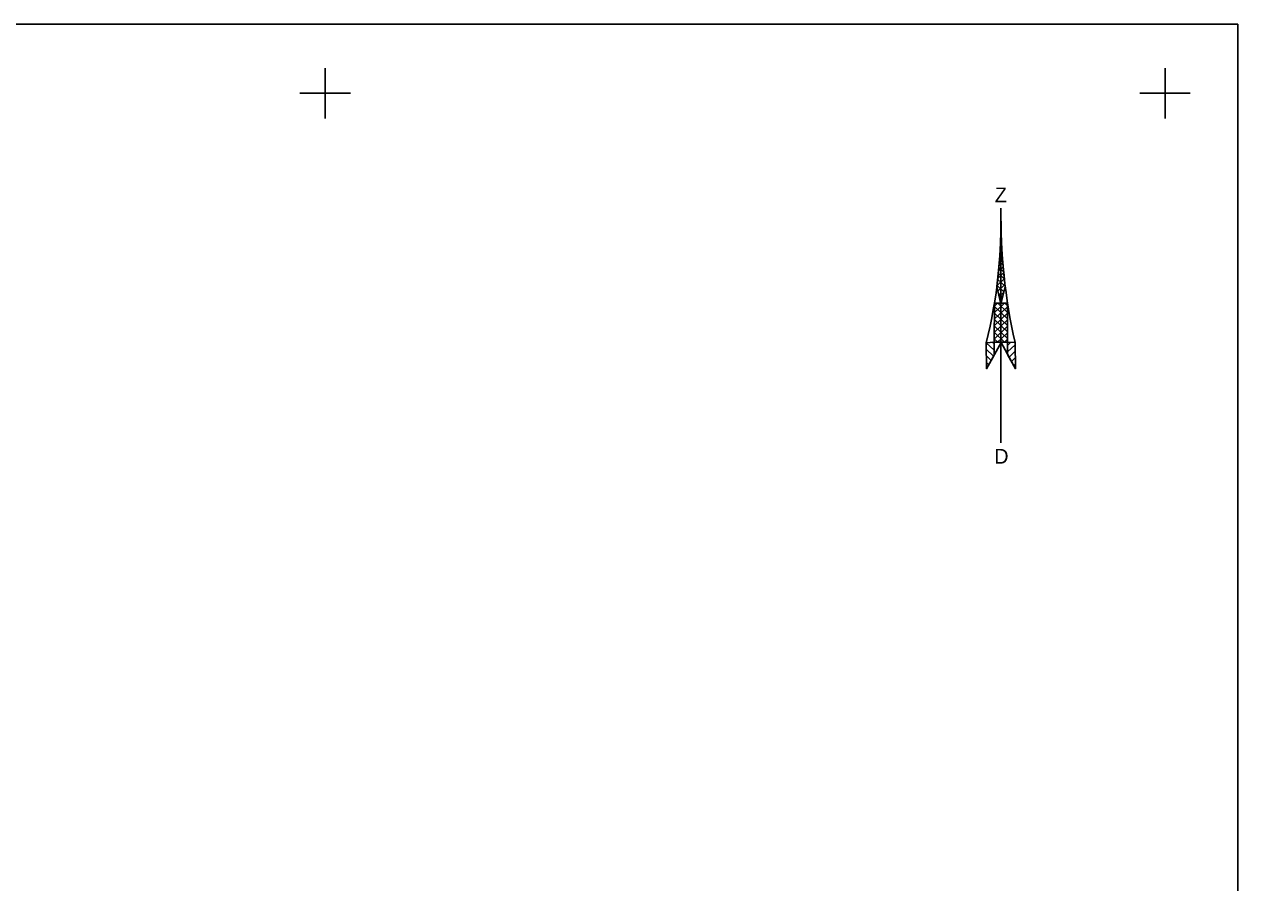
# Model space of a CAD drawing. Extents: x 503353 to 504004, y 304662 to 305049.
# Drawn here: x 503932.1 to 504004.3, y 304753 to 304804.1 of the extents above; entities that cross this region are included whole.
import ezdxf

# ---------------------------------------------------------------- set-up
doc = ezdxf.new("R2010")
doc.units = 0
doc.layers.add('GEOD_ELEM_####_####_#', color=7, linetype='Continuous')
doc.layers.add('RAMI_PLAN_####_TKST_#', color=7, linetype='Continuous')

msp = doc.modelspace()

# ---------------------------------------------------------------- linework, layer by layer
at = {"layer": 'GEOD_ELEM_####_####_#'}
for p, q in [((503950, 304801.5), (503950, 304800)), ((504000, 304801.5), (504000, 304800)), ((503948.5, 304800), (503950, 304800)), ((503950, 304800), (503950, 304798.5)), ((503950, 304800), (503951.5, 304800)), ((503998.5, 304800), (504000, 304800)), ((504000, 304800), (504000, 304798.5)), ((504000, 304800), (504001.5, 304800))]:
    msp.add_line(p, q, dxfattribs=at)
at = {"layer": 'RAMI_PLAN_####_TKST_#'}
for p, q in [((503990.224, 304793.174), (503990.224, 304779.204)), ((503990.227, 304791.474), (503990.25, 304791.451)), ((503990.182, 304790.672), (503990.284, 304790.772)), ((503990.184, 304790.737), (503990.292, 304790.634)), ((503990.202, 304791.082), (503990.265, 304791.14)), ((503990.204, 304791.104), (503990.268, 304791.043)), ((503990.123, 304789.844), (503990.331, 304790.041)), ((503990.136, 304790.005), (503990.354, 304789.8)), ((503990.156, 304790.264), (503990.302, 304790.397)), ((503990.164, 304790.363), (503990.317, 304790.222)), ((503990.038, 304788.987), (503990.393, 304789.322)), ((503990.072, 304789.29), (503990.426, 304788.953)), ((503990.088, 304789.419), (503990.362, 304789.681)), ((503990.108, 304789.645), (503990.388, 304789.377)), ((503989.99, 304788.548), (503990.425, 304788.963)), ((503989.993, 304788.59), (503990.407, 304788.194)), ((503990.032, 304788.939), (503990.475, 304788.515)), ((503990.051, 304788.217), (503990.466, 304788.617)), ((503990.071, 304788.128), (503990.327, 304787.881)), ((503990.123, 304787.9), (503990.399, 304788.163)), ((503989.834, 304786.554), (503990.622, 304787.301)), ((503989.837, 304786.943), (503990.437, 304787.513)), ((503989.841, 304787.334), (503990.027, 304787.513)), ((503989.841, 304787.321), (503990.624, 304786.577)), ((503990.048, 304787.513), (503990.624, 304786.965)), ((503990.185, 304787.626), (503990.245, 304787.57)), ((503990.196, 304787.582), (503990.267, 304787.652)), ((503990.457, 304787.513), (503990.622, 304787.355)), ((503989.826, 304785.766), (503990.624, 304786.528)), ((503989.831, 304786.161), (503990.624, 304786.915)), ((503989.834, 304786.554), (503990.625, 304785.799)), ((503989.837, 304786.934), (503990.625, 304786.189)), ((503989.823, 304785.376), (503990.625, 304786.138)), ((503989.826, 304785.783), (503990.452, 304785.188)), ((503989.831, 304786.166), (503990.627, 304785.41)), ((503990.033, 304785.188), (503990.625, 304785.75)), ((503989.354, 304785.155), (503989.376, 304783.606)), ((503989.357, 304785.155), (503989.82, 304784.718)), ((503989.376, 304783.606), (503990.237, 304785.179)), ((503989.735, 304785.184), (503989.821, 304785.102)), ((503989.823, 304785.396), (503990.043, 304785.188)), ((503990.237, 304785.179), (503991.094, 304783.606)), ((503990.439, 304785.188), (503990.627, 304785.365)), ((503990.625, 304784.607), (503991.075, 304785.033)), ((503990.627, 304784.994), (503990.824, 304785.184)), ((503991.094, 304783.606), (503991.072, 304785.179)), ((503989.359, 304784.764), (503989.788, 304784.363)), ((503989.364, 304784.371), (503989.648, 304784.105)), ((503990.714, 304784.299), (503991.079, 304784.652)), ((503990.853, 304784.047), (503991.084, 304784.266)), ((503989.371, 304783.975), (503989.508, 304783.847)), ((503989.376, 304783.613), (503989.385, 304783.621)), ((503990.992, 304783.792), (503991.091, 304783.882)), ((503991.094, 304783.608), (503991.094, 304783.608))]:
    msp.add_line(p, q, dxfattribs=at)
for points in [[(504004.329, 304661.504), (503807.145, 304661.504), (503807.145, 304804.108), (504004.329, 304804.108)], [(503990.223, 304787.473), (503989.983, 304788.505), (503990.093, 304789.46), (503990.163, 304790.334), (503990.225, 304791.474), (503990.246, 304791.474), (503990.302, 304790.397), (503990.418, 304789.029), (503990.48, 304788.48)], [(503989.843, 304787.513), (503990.622, 304787.513), (503990.627, 304785.186), (503989.821, 304785.191)], [(503989.821, 304785.191), (503989.819, 304784.416), (503989.376, 304783.606), (503989.354, 304785.155)], [(503990.627, 304785.186), (503990.625, 304784.456), (503991.094, 304783.606), (503991.072, 304785.179)]]:
    msp.add_lwpolyline(points, close=True, dxfattribs=at)
for centre, major_axis, start_param, end_param in [((503957.891, 304792.291), (32.345, 0), 6.048896, 6.311872), ((504028.562, 304792.807), (-38.341, 0), 6.273156, 6.494161)]:
    msp.add_ellipse(centre, major_axis=major_axis, ratio=0.950423, start_param=start_param, end_param=end_param, dxfattribs=at)

# ---------------------------------------------------------------- texts
for s, p in [('Z', (503989.869, 304793.515)), ('D', (503989.835, 304777.961))]:
    msp.add_text(s, height=0.878, rotation=360, dxfattribs=at).set_placement(p)

doc.saveas('drawing.dxf')
